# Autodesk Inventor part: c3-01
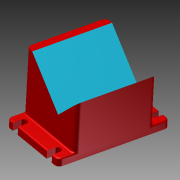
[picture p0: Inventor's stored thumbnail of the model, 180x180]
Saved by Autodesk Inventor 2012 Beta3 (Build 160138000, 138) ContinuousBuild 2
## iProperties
Created: 2010-11
Part Number: c3-01
Material: Default
Document SubType Name: Modeling
Designer: Beta-8540w
Density: 1 g/cm^3
Author: Beta-8540w
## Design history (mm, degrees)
sketch "Sketch1"
  geometry: L1 (-45, 0)-(45, 0); L2 (45, 0)-(45, 10); L3 (45, 10)-(-45, 10); L4 (-45, 10)-(-45, 0); L5 (-45, 10)-(-45, 90); L6 (-45, 90)-(-35, 90); L7 (-35, 90)-(14.497, 40.503); L8 (14.497, 40.503)-(45, 71.005); L9 (45, 71.005)-(45, 10); 2 further points
  constraints: 18 end point, 4 perpendicular, 3 collinear, 2 parallel, 2 point on line, 1 coincident, 1 horizontal, 1 midpoint
  dimensions: "d0" = 90 distance of L3.end L2.end; "d1" = 10 distance of L2.end L1.end; "d2" = 80 distance of L5.start L5.end; "d3" = 10 distance of L5.end L6.end; "d4" = 70 distance of L6.end L7.end; "d5" = 135 deg angle of L6 L7
extrude "Extrusion1" new body sketch "Sketch1" stored distance "d8" = 100; taper "d9" = 0 deg
extrude "Extrusion2" join sketch "Sketch1" stored distance "d10" = 140; taper "d11" = 0 deg
fillet "Fillet1" dims "d12" = 6
fillet "Fillet2" dims "d13" = 2
sketch "Sketch2"
  geometry: L1 (78, -2)-(0, -2) reference; L2 (-6, 4)-(-6, 132) reference; L3 (4.5, -2)-(13.5, -2); L4 (13.5, -2)-(13.5, 8); L5 (13.5, 8)-(4.5, 8); L6 (4.5, 8)-(4.5, -2); 2 further points
  constraints: 8 end point, 2 parallel, 1 horizontal, 1 horizontal alignment, 1 midpoint, 1 perpendicular, 1 point on line, 2 other
  dimensions: "d14" = 9 distance of L5.end L4.end; "d15" = 10 distance of L4.end L3.end; "d16" = 15 distance from line of point (9, 8) L2
extrude "Extrusion3" cut sketch "Sketch2" stored distance "d17" = 140; taper "d18" = 0 deg
mirror "Mirror1"
mirror "Mirror2"
body "Solid1"
